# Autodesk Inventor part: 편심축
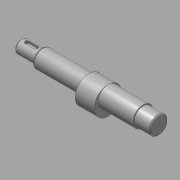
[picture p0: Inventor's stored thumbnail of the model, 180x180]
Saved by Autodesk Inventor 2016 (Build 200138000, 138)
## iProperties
Created: 2017-08
Part Number: 편심축
Material: 강철, 연강
Document SubType Name: Modeling
Designer: mduedu
Density: 1 g/cm^3
Appearance: 강철
Author: mduedu
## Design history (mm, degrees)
sketch "스케치1"
  geometry: L1 (0, 0)-(150, 0); L2 (150, 0)-(150, 8.5); L3 (150, 8.5)-(135, 8.5); L4 (135, 8.5)-(135, 9.5); L5 (135, 9.5)-(51, 9.5); L6 (51, 9.5)-(51, 8.5); L7 (51, 8.5)-(19, 8.5); L8 (19, 8.5)-(19, 6); L9 (19, 6)-(0, 6); L10 (0, 6)-(0, 0)
  constraints: 20 end point, 6 parallel, 2 collinear, 2 perpendicular, 1 horizontal
  dimensions: "d0" = 150 distance of L1.start L1.end; "d1" = 17 diameter of L3 L1; "d2" = 19 diameter of L5 L1; "d3" = 12 diameter of L9 L1; "d4" = 19 distance of L8.end L9.end; "d5" = 15 distance of L2.end L3.end; "d6" = 84 distance of L4.end L5.end
revolve "회전1" sketch "스케치1" stored, may be unused: angle "d7" = 90 deg
node "작업 평면1"
sketch "스케치2"
  geometry: C1 r 9.5 at (0, 0) reference; C2 r 13 at (0, -3.5); 1 further point
  constraints: 1 centre point, 1 tangent, 1 vertical alignment
  dimensions: "d8" = 3.5 distance of point (0, 0) C2.centre
extrude "돌출1" join sketch "스케치2" stored distance "d9" = 18; taper "d10" = 0 deg
chamfer "모따기1" distance "d11" = 1; stored, may be unused: second distance "d12" = 2, angle "d13" = 45 deg
node "작업 평면2"
sketch "스케치3"
  geometry: L1 (3.5, -2)-(-4.5, -2); L2 (-4.5, -2)-(-4.5, 2); L3 (-4.5, 2)-(3.5, 2); L4 (3.5, 2)-(3.5, -2); L5 (9.5, 6)-(9.5, -6) reference; A1 r 2 centre (3.5, 0) between (3.5, -2) and (3.5, 2); A2 r 2 centre (-4.5, 0) between (-4.5, 2) and (-4.5, -2); A3 r 2 centre (3.5, 0) between (3.5, 2) and (3.5, -2); A4 r 2 centre (-4.5, 0) between (-4.5, -2) and (-4.5, 2); 1 further point
  constraints: 8 end point, 8 point on circle, 4 centre point, 2 midpoint, 2 parallel, 1 horizontal, 1 horizontal alignment, 1 perpendicular
  dimensions: "d14" = 12 dimension on A2 A1; "d16" = 4 distance between parallel lines of L3 L1; "d17" = 4 distance edge to line of A1 L5
extrude "돌출2" cut sketch "스케치3" distance "d18" = 2.5; taper "d19" = 0 deg
chamfer "모따기2" distance "d20" = 1; stored, may be unused: second distance "d21" = 2, angle "d22" = 45 deg
chamfer "모따기3" distance "d23" = 1; stored, may be unused: second distance "d24" = 2, angle "d25" = 60 deg
fillet "모깎기1" dims "d26" = 0.5
hole "구멍1" diameter "d29" = 3.242; stored, may be unused: countersink angle "d33" = 90 deg, drill point angle "d35" = 118 deg; dims "d30" = 8, "d31" = 4, "d32" = 2, "d34" = 10, "d36" = 10, "d37" = 10
node "솔리드1"
node "절단 모서리 투영1"
other parameters: "d38" = -42
